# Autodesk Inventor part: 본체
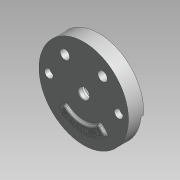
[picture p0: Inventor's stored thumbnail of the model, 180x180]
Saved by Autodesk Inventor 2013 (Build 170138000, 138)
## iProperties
Created: 2015-04
Part Number: 본체
Material: 알루미늄 6061
Document SubType Name: 모델링
Designer: Administrator
Mass: 1051.47 g
Surface Area: 1036.79 cm^2
Volume: 387.998 cm^3
Density: 2.71 g/cm^3
Author: Administrator
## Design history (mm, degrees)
sketch "스케치2"
  geometry: C1 r 95 at (0, 0); 1 further point
  constraints: 1 centre point, 1 coincident
  dimensions: "d0" = 190 diameter of C1
extrude "돌출1" new body sketch "스케치2" distance "d1" = 32; taper "d2" = 0 deg
sketch "스케치3"
  geometry: C1 r 95 at (0, 0) reference; C2 r 90 at (0, 0)
  constraints: 1 centre point, 1 coincident
  dimensions: "d3" = 180 diameter of C2
extrude "돌출2" cut sketch "스케치3" distance "d4" = 18; taper "d5" = 0 deg
sketch "스케치5"
  geometry: C1 r 90 at (0, 0) reference; C2 r 35 at (0, 0)
  constraints: 1 centre point, 1 coincident
  dimensions: "d8" = 70 diameter of C2
extrude "돌출3" join sketch "스케치5" distance "d9" = 10; taper "d10" = -10 deg
hole "구멍1" diameter "d13" = 23; stored, may be unused: countersink angle "d17" = 90 deg, drill point angle "d19" = 118 deg; dims "d11" = 10, "d12" = 10, "d14" = 6, "d15" = 50, "d16" = 15, "d18" = 8
sketch "스케치6"
  geometry: L1 (-59, -19)-(59, -19); L2 (-59, -19)-(-59, -14); L3 (-41, -19)-(-41, -14); L4 (41, -19)-(41, -14); L5 (59, -19)-(59, -14); A1 r 41 centre (0, -19) between (-41, -19) and (41, -19); A2 r 59 centre (0, -19) between (-59, -19) and (59, -19); A3 r 9 centre (-50, -14) between (-41, -14) and (-59, -14); A4 r 9 centre (50, -14) between (59, -14) and (41, -14); 1 further point
  constraints: 10 end point, 8 point on circle, 4 centre point, 4 tangent, 3 parallel, 2 point on line, 1 coincident, 1 horizontal, 1 perpendicular
  dimensions: "d22" = 82 diameter of A1; "d27" = 5 distance of L4.end L4.start; "d140" = 19 distance from line of L1 point (0, 0)
sketch "스케치8"
  geometry: L1 (-89.658, -7.844)-(-94.638, -8.28); L2 (0, 0)-(114.484, 0); L3 (89.658, -7.844)-(94.638, -8.28); L4 (0, 0)-(108.89, 0); A1 r 90 centre (0, 0) between (-89.658, -7.844) and (89.658, -7.844) reference; A2 r 95 centre (0, 0) between (-94.638, -8.28) and (94.638, -8.28) reference
  constraints: 8 end point, 4 point on circle, 2 horizontal
  dimensions: "d33" = 175 deg angle of L1 L2; "d34" = 5 deg angle of L3 L4
extrude "돌출6" cut sketch "스케치8" distance "d35" = 5; taper "d36" = 0 deg
extrude "돌출8" cut sketch "스케치6" distance "d39" = 7; taper "d40" = 0 deg
sketch "스케치9"
  geometry: L1 (41, -19)-(41, -14) reference; L2 (-89.196, 12)-(-40.249, 12); L3 (40.249, 12)-(89.196, 12); C1 r 35 at (0, 0) reference; A1 r 90 centre (0, 0) between (-89.196, 12) and (89.196, 12) reference; A2 r 42 centre (0, 0) between (40.249, 12) and (-40.249, 12)
  constraints: 4 end point, 4 point on circle, 1 centre point, 1 coincident, 1 collinear, 1 perpendicular
  dimensions: "d42" = 12 distance from line of A2.centre L2; "d43" = 12 distance from line of C1.centre L3
extrude "돌출9" cut sketch "스케치9" distance "d44" = 7; taper "d45" = 0 deg
sketch "스케치11"
  geometry: C1 r 11.5 at (0, 0) reference; 2 further points
  constraints: 2 horizontal alignment
  dimensions: "d46" = 148 distance of point (74, 0) point (-74, 0); "d48" = 74 distance of point (-74, 0) C1.centre (= 0.5 x d46)
hole "구멍2" sketch "스케치11" at (-74, 0), (74, 0) diameter "d49" = 11; stored, may be unused: countersink angle "d53" = 90 deg, drill point angle "d55" = 118 deg; dims "d50" = 6, "d51" = 18, "d52" = 11, "d54" = 8
sketch "스케치12"
  geometry: C1 r 15 at (-40, 52); C2 r 15 at (40, 52); A1 r 42 centre (0, 0) between (40.249, 12) and (-40.249, 12) reference
  constraints: 2 centre point
  dimensions: "d56" = 30 diameter of C1; "d57" = 30 diameter of C2; "d58" = 80 distance of C1.centre C2.centre; "d59" = 40 horizontal distance of A1.centre C1.centre (= 0.5 x d58); "d60" = 52 vertical distance of A1.centre C2.centre; "d61" = 52 vertical distance of A1.centre C1.centre
extrude "돌출10" join sketch "스케치12" distance "d62" = 25; taper "d63" = 0 deg
hole "구멍3" diameter "d66" = 20; stored, may be unused: countersink angle "d70" = 90 deg, drill point angle "d72" = 118 deg; dims "d64" = 10, "d65" = 10, "d67" = 6, "d68" = 18, "d69" = 11, "d71" = 8
hole "구멍4" diameter "d75" = 20; stored, may be unused: countersink angle "d79" = 90 deg, drill point angle "d81" = 118 deg; dims "d73" = 10, "d74" = 10, "d76" = 6, "d77" = 18, "d78" = 11, "d80" = 8
sketch "스케치14"
  geometry: L1 (-6, -17.697)-(-6, 19.707); L2 (6, 19.707)-(6, -17.697); L3 (6, 19.707)-(-6, 19.707); L4 (6, -17.697)-(-6, -17.697); C1 r 10 at (0, 0) reference; 1 further point
  constraints: 8 end point, 2 parallel, 1 perpendicular, 1 vertical
  dimensions: "d82" = 12 distance between parallel lines of L2 L1; "d84" = 6 distance from line of L1 C1.centre (= 0.5 x d82)
extrude "돌출11" cut sketch "스케치14" distance "d85" = 3; taper "d86" = 0 deg
sketch "스케치15"
  geometry: L1 (-23.35, 6)-(20.051, 6); L2 (-23.35, -6)-(20.051, -6); L3 (20.051, -6)-(20.051, 6); L4 (-23.35, -6)-(-23.35, 6); C1 r 10 at (0, 0) reference; 1 further point
  constraints: 8 end point, 2 perpendicular, 1 horizontal, 1 parallel
  dimensions: "d87" = 6 distance from line of L1 C1.centre (= 0.5 x d88); "d88" = 12 distance between parallel lines of L2 L1
extrude "돌출12" cut sketch "스케치15" distance "d89" = 3; taper "d90" = 0 deg
sketch "스케치16"
  geometry: C1 r 5.5 at (74, 0) reference; C2 r 5.5 at (-74, 0) reference; C3 r 9 at (-74, 0); C4 r 9 at (74, 0)
  constraints: 2 centre point, 2 coincident
  dimensions: "d91" = 18 diameter of C3; "d92" = 18 diameter of C4
extrude "돌출13" join sketch "스케치16" distance "d93" = 18; taper "d94" = 0 deg
fillet "모깎기1" dims "d95" = 10
fillet "모깎기2" dims "d96" = 10
fillet "모깎기3" dims "d97" = 3
fillet "모깎기4" dims "d98" = 3
chamfer "모따기1" distance "d99" = 1; stored, may be unused: second distance "d100" = 2, angle "d101" = 45 deg
chamfer "모따기2" distance "d102" = 1; stored, may be unused: second distance "d103" = 2, angle "d104" = 45 deg
chamfer "모따기3" distance "d105" = 1; stored, may be unused: second distance "d106" = 2, angle "d107" = 45 deg
fillet "모깎기5" dims "d108" = 3
fillet "모깎기6" dims "d109" = 3
sketch "스케치17"
  geometry: L1 (0, 0)-(117.38, 0); L2 (0, 0)-(130.203, 0); L3 (-36.062, -36.062)-(-50.912, -50.912); L4 (36.062, -36.062)-(50.912, -50.912); C1 r 12.5 at (0, 0) reference; A1 r 51 centre (0, 0) between (-36.062, -36.062) and (36.062, -36.062); A2 r 72 centre (0, 0) between (-50.912, -50.912) and (50.912, -50.912)
  constraints: 8 end point, 4 point on circle, 2 centre point, 2 coincident, 2 horizontal
  dimensions: "d110" = 102 diameter of A1; "d114" = 72 radius of A2
extrude "돌출14" join sketch "스케치17" distance "d116" = 5; taper "d117" = 0 deg
fillet "모깎기7" dims "d118" = 5
fillet "모깎기10" dims "d124" = 3
fillet "모깎기11" dims "d125" = 5
sketch "스케치21"
  geometry: L1 (0, 0)-(85.902, 0); L2 (-1.365, -1.365)-(92.871, -1.365); A1 r 68 centre (0, 0) between (67.986, -1.365) and (68, 0); A2 r 68 centre (0, 0) between (-48.083, -48.083) and (48.083, -48.083); 1 further point
  constraints: 4 end point, 4 point on circle, 2 centre point, 2 horizontal, 2 point on line, 1 coincident, 1 other
feature "엠보싱2" sketch "스케치21" dims "d0" = 190, "d133" = 0.5, "d134" = 0
fillet "모깎기12" dims "d135" = 3
fillet "모깎기13" dims "d136" = 0.3
fillet "모깎기14" dims "d137" = 1
fillet "모깎기15" dims "d141" = 3
node "솔리드1"
node "솔리드 본체"
node "곡면 본체"
other parameters: "d41" = 84, "d111" = 144, "d112" = 135 deg, "d113" = 45 deg, "d128" = 136, "d130" = 136
